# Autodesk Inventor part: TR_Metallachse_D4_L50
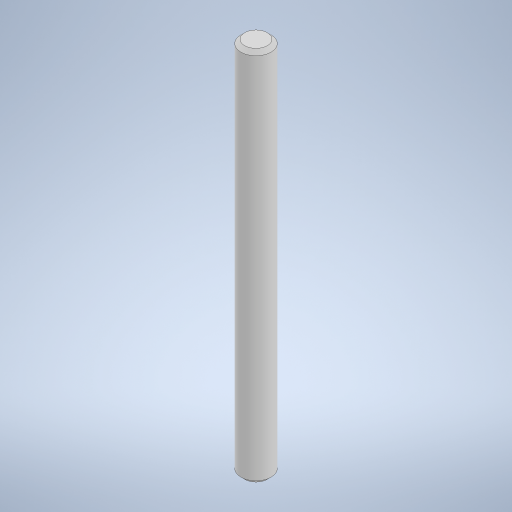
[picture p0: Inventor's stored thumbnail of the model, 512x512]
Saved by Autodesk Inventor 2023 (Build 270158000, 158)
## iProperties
Created: 2023-11
Part Number: TR_Metallachse_D4_L50
Material: Generisch
Document SubType Name: Modeling
Designer: Greiner
Density: 1 g/cm^3
Appearance: Vorgabe
Author: Greiner
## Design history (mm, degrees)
sketch "Skizze1"
  geometry: C1 r 2 at (0, 0); 1 further point
  constraints: 1 centre point, 1 coincident
  dimensions: "d0" = 4 diameter of C1 (= AchsDurchmesser)
extrude "Extrusion1" new body sketch "Skizze1" distance "d1" = 50; taper "d2" = 0 deg
chamfer "Fase1" distance "d3" = 0.5 (= AchsFase); stored, may be unused: second distance "d4" = 2, angle "d5" = 45 deg
node "Volumenkörper1"
other parameters: "Radius" = 2.075 [user parameter], "Fasen" = 0.5 [user parameter], "Dicke" = 0.8 [user parameter], "Breitloch" = 2 [user parameter], "Langloch" = 32 [user parameter], "AchteckUmkreis" = 6 [user parameter], "DAchsAufnahme" = 4.1 [user parameter], "AchsDurchmesser" = 4 [user parameter; used in 1 equation term], "AchsFase" = 0.5 [user parameter; used in 1 equation term]
